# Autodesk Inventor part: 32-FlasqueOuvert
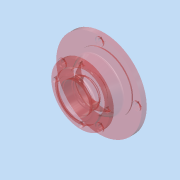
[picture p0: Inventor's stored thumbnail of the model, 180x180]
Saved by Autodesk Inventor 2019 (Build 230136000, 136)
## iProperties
Created: 2023-02
Part Number: 32-FlasqueOuvert
Material: Générique
Document SubType Name: Modeling
Designer: Thier
Density: 1 g/cm^3
Appearance: Rouge foncé
Author: Thier
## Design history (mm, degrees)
sketch "Esquisse1"
  geometry: L1 (47, 22)-(47, 15); L2 (47, 15)-(31.5, 15); L3 (31.5, 15)-(31.5, 0); L4 (31.5, 0)-(0, 0); L5 (0, 0)-(0, 5.797); L6 (14.5, 8.5)-(21, 8.5); L7 (21, 8.5)-(21, 13.5); L8 (21, 13.5)-(23, 13.5); L9 (23, 13.5)-(23, 26.5); L10 (23, 26.5)-(24, 26.5); L11 (24, 26.5)-(24, 31); L12 (24, 31)-(28.5, 31); L13 (28.5, 31)-(28.5, 27); L14 (28.5, 27)-(36, 27); L15 (36, 27)-(36, 22); L16 (36, 22)-(47, 22); L17 (14.5, 8.5)-(14.5, 3.5); L18 (14.5, 3.5)-(0, 3.5); 1 further point
  constraints: 36 end point, 13 perpendicular, 3 parallel, 2 vertical, 1 coincident, 1 point on line
  dimensions: "d0" = 94 diameter of L1 L5; "d1" = 72 diameter of L15 L5; "d2" = 57 diameter of L13 L5; "d3" = 48 diameter of L11 L5; "d4" = 46 diameter of L9 L5; "d5" = 42 diameter of L7 L5; "d6" = 29 diameter of L17 L5; "d7" = 7 distance of L1.start L1.end; "d8" = 5 distance of L14.end L15.end; "d9" = 4 distance of L12.end L13.end; "d10" = 31 distance between parallel lines of L4 L12; "d11" = 4.5 distance of L10.end L11.end; "d12" = 13 distance of L8.end L9.end; "d13" = 5 distance of L6.end L7.end; "d14" = 5 distance of L6.start L17.end; "d16" = 15 distance of L2.end L3.end (derived); "d17" = 63 diameter of L3 L5
revolve "Révolution1" sketch "Esquisse1" stored, may be unused: angle "d15" = 90 deg
chamfer "Chanfrein1" distance "d18" = 9; stored, may be unused: second distance "d19" = 15, angle "d20" = 45 deg
fillet "Congé1" dims "d24" = 3
fillet "Congé2" dims "d25" = 5
fillet "Congé3" dims "d26" = 3
sketch "Esquisse3"
  geometry: C1 r 47 at (0, 0) reference; 2 further points
  dimensions: "d46" = 0 vertical distance of C1.centre point (-42, 0); "d47" = 42 distance of C1.centre point (-42, 0)
hole "Perçage2" sketch "Esquisse3" at (-42, 0) diameter "d39" = 7; stored, may be unused: countersink angle "d43" = 90 deg, drill point angle "d45" = 118 deg; dims "d40" = 6, "d41" = 4, "d42" = 2, "d44" = 8
pattern_circular "Réseau circulaire2" dims angle "d49" = 360 deg
sketch "Esquisse4"
  geometry: C1 r 23.374 at (0, 0) reference; 2 further points
  dimensions: "d58" = 0 distance of point (0, 0) point (0, 0); "d59" = 0 distance of C1.centre point (0, 0)
hole "Perçage3" sketch "Esquisse4" at (0, 0) diameter "d51" = 35; stored, may be unused: countersink angle "d55" = 90 deg, drill point angle "d57" = 118 deg; dims "d52" = 6, "d53" = 4, "d54" = 2, "d56" = 8
sketch "Esquisse5"
  geometry: L1 (24.808, 22.385)-(40, -8); L2 (40, -8)-(69, -8); L3 (69, -8)-(69, -16); L4 (69, -16)-(45, -16); L5 (45, -16)-(45, -18); L6 (45, -18)-(39, -18); L7 (39, -18)-(24.808, 10.385); L8 (24.808, 10.385)-(24.808, 22.385); L9 (0, 0)-(0, -49.39); L10 (-24, 31)-(24, 31) reference
  constraints: 18 end point, 4 perpendicular, 2 vertical, 1 horizontal, 1 parallel, 1 point on line
  dimensions: "d60" = 138 diameter of L3 L9; "d61" = 90 diameter of L5 L9; "d62" = 78 diameter of L6.end L9; "d63" = 80 diameter of L1.end L9; "d65" = 8 distance of L2.end L3.end; "d66" = 10 distance between parallel lines of L6 L2; "d67" = 49 distance between parallel lines of L10 L6
revolve "Révolution2" sketch "Esquisse5" stored, may be unused: angle "d68" = 90 deg
fillet "Congé4" dims "d69" = 3
fillet "Congé5" dims "d70" = 3
sketch "Esquisse6"
  geometry: C1 r 69 at (0, 0) reference; 2 further points
  dimensions: "d78" = 0 horizontal distance of C1.centre point (0, 60); "d79" = 60 distance of point (0, 60) C1.centre
hole "Perçage4" sketch "Esquisse6" at (0, 60) diameter "d71" = 7; stored, may be unused: countersink angle "d75" = 90 deg, drill point angle "d77" = 118 deg; dims "d72" = 6, "d73" = 13, "d74" = 2, "d76" = 8
pattern_circular "Réseau circulaire3" dims angle "d81" = 360 deg
sketch "Esquisse7"
  geometry: C1 r 3.5 at (60, 0) reference; C2 r 6.5 at (60, 0); 1 further point
  constraints: 1 centre point, 1 coincident
  dimensions: "d83" = 13 diameter of C2
extrude "Extrusion1" cut sketch "Esquisse7" distance "d84" = 2; taper "d85" = 0 deg
pattern_circular "Réseau circulaire4" dims angle "d87" = 360 deg
node "Solide1"
